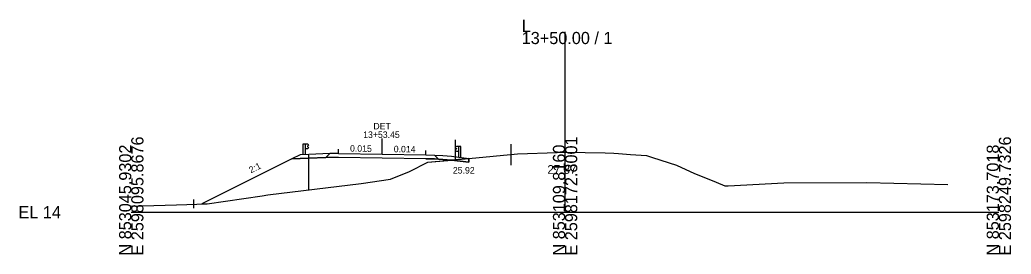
# Model space of a CAD drawing. Extents: x -26 to 1203, y -10 to 9526.
# Drawn here: x -25.7 to 202.8, y 3490.3 to 3544.4 of the extents above; entities that cross this region are included whole.
import ezdxf

# ---------------------------------------------------------------- set-up
doc = ezdxf.new("R2010")
doc.units = 0
for name, color, linetype in [('Exist Cross Section Cell', 7, 'Continuous'), ('Exist XS Center Line Elevation Label', 7, 'Continuous'), ('Exist XS Ground Line', 7, 'Continuous'), ('Prop XS Alignment Label', 7, 'Continuous'), ('Prop XS Ditch Standard Text', 7, 'Continuous'), ('Prop XS Earthwork Shape', 7, 'Continuous'), ('Prop XS EOT Tick Mark', 7, 'Continuous'), ('Prop XS Exc Vertical Line 1', 7, 'Continuous'), ('Prop XS Exc Vertical Line 2', 7, 'Continuous'), ('Prop XS Finish Grade', 7, 'Continuous'), ('Prop XS Finish Grade Earthwork', 7, 'Continuous'), ('Prop XS Finish Grade Paved Shoulder', 7, 'Continuous'), ('Prop XS Finish Grade Pavement', 7, 'Continuous'), ('Prop XS Guardrail', 7, 'Continuous'), ('Prop XS Pvmt Edge Slope', 7, 'Continuous'), ('Prop XS SE Text', 7, 'Continuous'), ('Prop XS Side Slope Text', 7, 'Continuous'), ('Prop XS Station Labels', 7, 'Continuous'), ('Prop XS Subgrade Earthwork', 7, 'Continuous'), ('Scratch_Level_1', 7, 'Continuous'), ('Scratch_Level_2', 7, 'Continuous')]:
    doc.layers.add(name, color=color, linetype=linetype)

msp = doc.modelspace()

# ---------------------------------------------------------------- linework, layer by layer
at = {"layer": 'Exist Cross Section Cell'}
for p, q in [((100, 3500), (100, 3541.61)), ((0, 3500), (100, 3500)), ((100, 3500), (200, 3500))]:
    msp.add_line(p, q, dxfattribs=at)
at = {"layer": 'Exist XS Ground Line'}
for p, q in [((77.81, 3512.42), (89.01, 3513.51)), ((89.01, 3513.51), (98.2, 3513.81)), ((98.2, 3513.81), (100.05, 3513.87)), ((100.05, 3513.87), (109.27, 3513.69)), ((109.27, 3513.69), (111.23, 3513.65)), ((111.23, 3513.65), (112.3, 3513.57)), ((112.3, 3513.57), (115.07, 3513.34)), ((115.07, 3513.34), (118.75, 3513.07)), ((118.75, 3513.07), (120.18, 3512.62)), ((120.18, 3512.62), (125.69, 3510.82)), ((64.14, 3509.42), (68.39, 3511.53)), ((68.39, 3511.53), (77.81, 3512.42)), ((125.69, 3510.82), (129.87, 3508.97)), ((59.76, 3507.61), (64.14, 3509.42)), ((129.87, 3508.97), (133.9, 3507.29)), ((31.46, 3504.02), (52.98, 3506.62)), ((52.98, 3506.62), (59.76, 3507.61)), ((133.9, 3507.29), (136.33, 3506.29)), ((136.33, 3506.29), (136.8, 3506.09)), ((136.8, 3506.09), (137.57, 3506.1)), ((137.57, 3506.1), (150.42, 3506.76)), ((150.42, 3506.76), (169.6, 3506.89)), ((169.6, 3506.89), (188.23, 3506.41)), ((17.51, 3501.96), (30.18, 3503.81)), ((30.18, 3503.81), (31.46, 3504.02)), ((0, 3501.36), (10.39, 3501.72)), ((10.39, 3501.72), (17.51, 3501.96))]:
    msp.add_line(p, q, dxfattribs=at)
at = {"layer": 'Prop XS Earthwork Shape'}
for points in [[(37.03, 3512.3), (16.26, 3501.92), (17.51, 3501.96), (30.18, 3503.81), (31.46, 3504.02), (52.98, 3506.62), (59.76, 3507.61), (64.14, 3509.42), (68.39, 3511.53), (73.88, 3512.05), (73.84, 3512.05), (71.84, 3512.2), (70.86, 3512.27), (69.93, 3512.29), (67.93, 3512.32), (57.84, 3512.46), (47.74, 3512.61), (45.74, 3512.64), (44.84, 3512.65), (40.92, 3512.48), (38.92, 3512.39)], [(73.88, 3512.05), (77.81, 3511.56), (77.81, 3512.42)]]:
    msp.add_lwpolyline(points, close=True, dxfattribs=at)
at = {"layer": 'Prop XS EOT Tick Mark'}
for p, q in [((47.74, 3513.53), (47.74, 3514.53)), ((67.93, 3513.23), (67.93, 3514.23))]:
    msp.add_line(p, q, dxfattribs=at)
at = {"layer": 'Prop XS Exc Vertical Line 1'}
msp.add_line((14.33, 3502.97), (14.33, 3500.97), dxfattribs=at)
at = {"layer": 'Prop XS Exc Vertical Line 2'}
msp.add_line((87.51, 3515.74), (87.51, 3510.82), dxfattribs=at)
at = {"layer": 'Prop XS Finish Grade'}
for p, q in [((38.92, 3513.25), (37.03, 3512.3)), ((40.92, 3513.34), (38.92, 3513.25)), ((45.74, 3513.56), (40.92, 3513.34)), ((69.93, 3513.2), (71.84, 3513.06)), ((71.84, 3513.06), (73.84, 3512.92)), ((73.84, 3512.92), (77.81, 3512.42))]:
    msp.add_line(p, q, dxfattribs=at)
at = {"layer": 'Prop XS Finish Grade Earthwork'}
msp.add_line((37.03, 3512.3), (16.26, 3501.92), dxfattribs=at)
at = {"layer": 'Prop XS Finish Grade Paved Shoulder'}
for p, q in [((47.74, 3513.53), (45.74, 3513.56)), ((67.93, 3513.23), (69.93, 3513.2))]:
    msp.add_line(p, q, dxfattribs=at)
at = {"layer": 'Prop XS Finish Grade Pavement'}
for p, q in [((47.74, 3513.53), (57.84, 3513.37)), ((57.84, 3513.37), (67.93, 3513.23))]:
    msp.add_line(p, q, dxfattribs=at)
at = {"layer": 'Prop XS Guardrail'}
for p, q in [((39.6, 3515.78), (40.1, 3515.78)), ((39.6, 3513.28), (39.6, 3515.78)), ((40.1, 3515.78), (40.6, 3515.78)), ((40.1, 3515.78), (40.1, 3513.28)), ((40.6, 3515.78), (40.89, 3515.58)), ((40.89, 3515.46), (40.6, 3515.26)), ((40.6, 3515.26), (40.6, 3515.17)), ((40.6, 3515.17), (40.89, 3514.97)), ((40.89, 3514.85), (40.6, 3514.65)), ((40.89, 3515.58), (40.92, 3515.52)), ((40.92, 3515.52), (40.89, 3515.46)), ((40.89, 3514.97), (40.92, 3514.91)), ((40.92, 3514.91), (40.89, 3514.85)), ((74.68, 3515), (74.65, 3514.94)), ((74.65, 3514.94), (74.68, 3514.88)), ((74.97, 3515.2), (74.68, 3515)), ((74.68, 3514.88), (74.97, 3514.68)), ((75.47, 3515.2), (74.97, 3515.2)), ((75.97, 3515.2), (75.47, 3515.2)), ((75.47, 3515.2), (75.47, 3512.7)), ((75.97, 3512.7), (75.97, 3515.2)), ((40.6, 3514.65), (40.1, 3514.65)), ((74.68, 3514.39), (74.65, 3514.33)), ((74.65, 3514.33), (74.68, 3514.27)), ((74.97, 3514.59), (74.68, 3514.39)), ((74.68, 3514.27), (74.97, 3514.07)), ((74.97, 3514.68), (74.97, 3514.59)), ((74.97, 3514.07), (75.47, 3514.07))]:
    msp.add_line(p, q, dxfattribs=at)
at = {"layer": 'Prop XS Pvmt Edge Slope'}
for p, q in [((45.74, 3513.56), (44.84, 3512.65)), ((69.93, 3513.2), (70.86, 3512.27))]:
    msp.add_line(p, q, dxfattribs=at)
at = {"layer": 'Prop XS Side Slope Text'}
msp.add_line((57.84, 3513.37), (57.84, 3517.03), dxfattribs=at)
at = {"layer": 'Prop XS Subgrade Earthwork'}
for p, q in [((44.84, 3512.65), (40.92, 3512.48)), ((45.74, 3512.64), (44.84, 3512.65)), ((47.74, 3512.61), (45.74, 3512.64)), ((57.84, 3512.46), (47.74, 3512.61)), ((38.92, 3512.39), (37.03, 3512.3)), ((40.92, 3512.48), (38.92, 3512.39)), ((67.93, 3512.32), (57.84, 3512.46)), ((67.93, 3512.32), (69.93, 3512.29)), ((69.93, 3512.29), (70.86, 3512.27)), ((70.86, 3512.27), (71.84, 3512.2)), ((71.84, 3512.2), (73.84, 3512.05)), ((73.84, 3512.05), (77.81, 3511.56)), ((77.81, 3512.42), (77.81, 3511.56))]:
    msp.add_line(p, q, dxfattribs=at)
at = {"layer": 'Scratch_Level_1'}
for points in [[(38.92, 3513.25), (37.03, 3512.3), (38.92, 3512.39), (40.92, 3512.48), (44.84, 3512.65), (45.74, 3513.56), (40.92, 3513.34)], [(77.81, 3512.42), (77.81, 3511.56), (73.84, 3512.05), (71.84, 3512.2), (70.86, 3512.27), (69.93, 3513.2), (71.84, 3513.06), (73.84, 3512.92)]]:
    msp.add_lwpolyline(points, close=True, dxfattribs=at)
at = {"layer": 'Scratch_Level_2'}
for p, q in [((74.69, 3516.73), (74.69, 3512.13)), ((40.85, 3513.15), (40.85, 3505.15))]:
    msp.add_line(p, q, dxfattribs=at)

# ---------------------------------------------------------------- texts
at = {"layer": 'Exist Cross Section Cell'}
for s, p in [('L', (90, 3541.61)), ('13+50.00 / 1', (90, 3538.81)), ('EL 14', (-26, 3498.6))]:
    msp.add_text(s, height=2.8, dxfattribs=at).set_placement(p)
for s, p in [('E 2598095.8676', (2.8, 3490)), ('E 2598172.8001', (102.8, 3490)), ('E 2598249.7326', (202.8, 3490)), ('N 853045.9302', (0, 3490)), ('N 853109.8160', (100, 3490)), ('N 853173.7018', (200, 3490))]:
    msp.add_text(s, height=2.8, rotation=90, dxfattribs=at).set_placement(p)
at = {"layer": 'Exist XS Center Line Elevation Label'}
msp.add_text('27.87', height=2, dxfattribs=at).set_placement((95.93, 3508.87))
at = {"layer": 'Prop XS Alignment Label'}
msp.add_text('DET', height=1.5, dxfattribs=at).set_placement((55.81, 3519.12))
at = {"layer": 'Prop XS Ditch Standard Text'}
msp.add_text('25.92', height=1.5, dxfattribs=at).set_placement((74.14, 3508.92))
at = {"layer": 'Prop XS SE Text'}
for s, rotation, p in [('0.015', 359.1325, (50.42, 3513.99)), ('0.014', 359.1948, (60.5, 3513.84))]:
    msp.add_text(s, height=1.5, rotation=rotation, dxfattribs=at).set_placement(p)
at = {"layer": 'Prop XS Side Slope Text'}
msp.add_text('2:1', height=1.5, rotation=26.5651, dxfattribs=at).set_placement((27.58, 3508.95))
at = {"layer": 'Prop XS Station Labels'}
msp.add_text('13+53.45', height=1.5, dxfattribs=at).set_placement((53.46, 3517.15))

doc.saveas('drawing.dxf')
